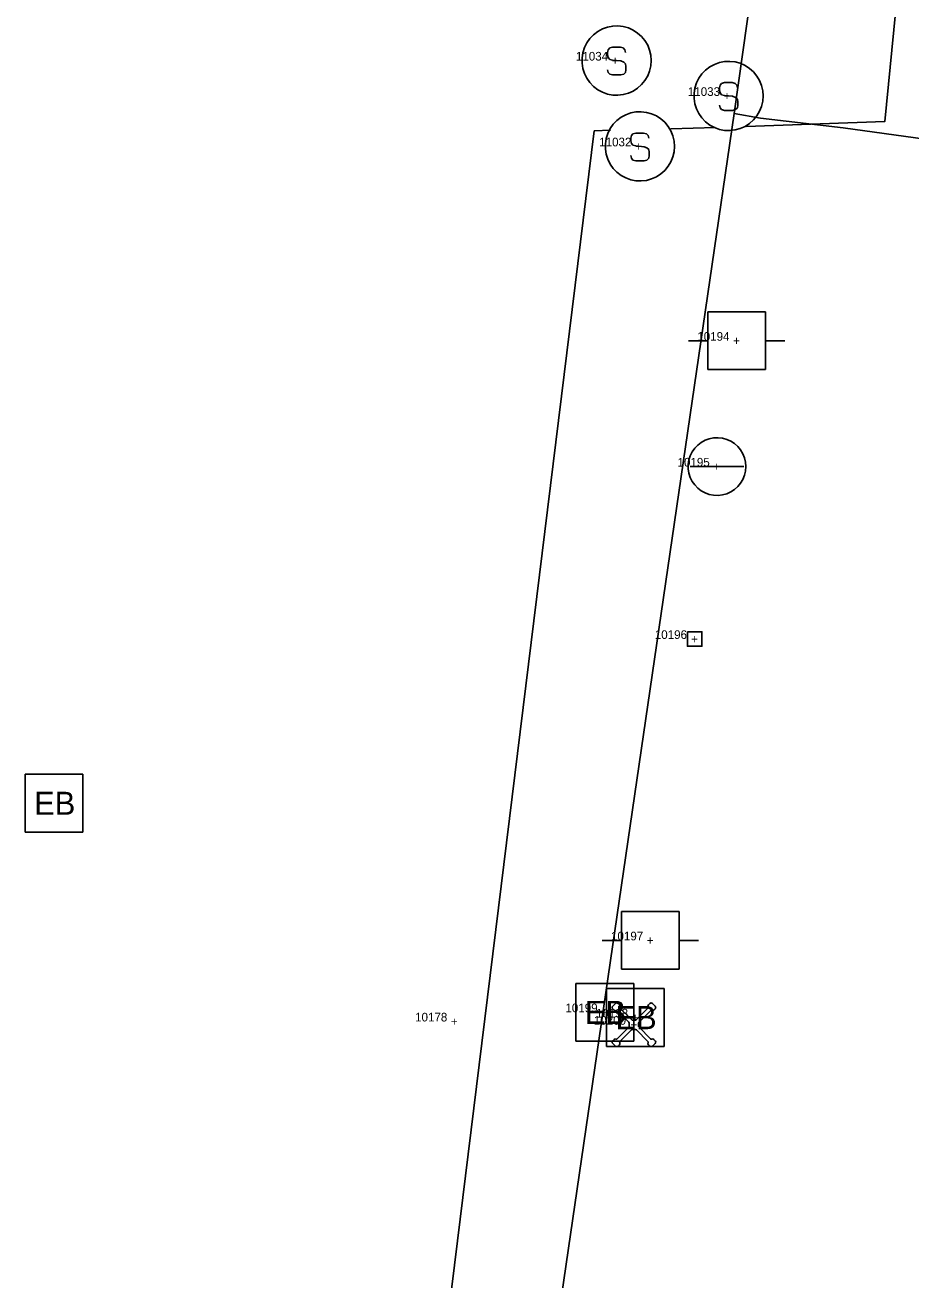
# Model space of a CAD drawing. Extents: x 1795905 to 1799611, y 243768 to 252016.
# Drawn here: x 1797887.3 to 1798040.7, y 247920.8 to 248138 of the extents above; entities that cross this region are included whole.
import ezdxf

# ---------------------------------------------------------------- set-up
doc = ezdxf.new("R2010")
doc.units = 0
for name, color, linetype in [('LS-SURVEY POINT', 7, 'Continuous'), ('OHUT', 7, 'Continuous'), ('TOPO', 7, 'Continuous'), ('UGUT', 7, 'Continuous'), ('UGUTTXT', 7, 'Continuous')]:
    doc.layers.add(name, color=color, linetype=linetype)

msp = doc.modelspace()

# ---------------------------------------------------------------- linework, layer by layer
at = {"layer": 'OHUT'}
for p, q in [((1798005.57, 248088.37), (1798015.57, 248088.37)), ((1798005.57, 248078.37), (1798005.57, 248088.37)), ((1798015.57, 248088.37), (1798015.57, 248078.37)), ((1798002.24, 248083.37), (1798005.57, 248083.37)), ((1798015.57, 248083.37), (1798018.91, 248083.37)), ((1798015.57, 248078.37), (1798005.57, 248078.37)), ((1797990.63, 247984.55), (1798000.63, 247984.55)), ((1797990.63, 247974.55), (1797990.63, 247984.55)), ((1798000.63, 247984.55), (1798000.63, 247974.55)), ((1797987.3, 247979.55), (1797990.63, 247979.55)), ((1798000.63, 247979.55), (1798003.97, 247979.55)), ((1798000.63, 247974.55), (1797990.63, 247974.55))]:
    msp.add_line(p, q, dxfattribs=at)
at = {"layer": 'TOPO'}
msp.add_lwpolyline([(1798002.04, 248032.99), (1798004.54, 248032.99), (1798004.54, 248030.49), (1798002.04, 248030.49)], close=True, dxfattribs=at)
at = {"layer": 'UGUT'}
for p, q in [((1797988.19, 248132.84), (1797988.19, 248133.29)), ((1797988.32, 248132.39), (1797988.19, 248132.84)), ((1797988.58, 248132.07), (1797988.32, 248132.39)), ((1797990.94, 248134.06), (1797990.43, 248134.19)), ((1797991.2, 248133.74), (1797990.94, 248134.06)), ((1797991.33, 248133.29), (1797991.2, 248133.74)), ((1797988.19, 248130.28), (1797988.32, 248129.83)), ((1797989.09, 248131.95), (1797988.58, 248132.07)), ((1797990.5, 248131.82), (1797989.09, 248131.95)), ((1797990.5, 248131.82), (1797991.01, 248131.63)), ((1797991.33, 248131.31), (1797991.01, 248131.63)), ((1797991.39, 248130.86), (1797991.33, 248131.31)), ((1797991.33, 248129.83), (1797991.39, 248130.28)), ((1797991.39, 248130.28), (1797991.39, 248130.86)), ((1797988.32, 248129.83), (1797988.58, 248129.51)), ((1797988.58, 248129.51), (1797989.09, 248129.39)), ((1797989.09, 248129.39), (1797990.5, 248129.39)), ((1797990.5, 248129.39), (1797991.01, 248129.51)), ((1797991.01, 248129.51), (1797991.33, 248129.83)), ((1798010.32, 248127.94), (1798009.81, 248128.06)), ((1798010.58, 248127.62), (1798010.32, 248127.94)), ((1798007.57, 248126.72), (1798007.57, 248127.17)), ((1798007.7, 248126.27), (1798007.57, 248126.72)), ((1798007.95, 248125.95), (1798007.7, 248126.27)), ((1798008.47, 248125.82), (1798007.95, 248125.95)), ((1798009.87, 248125.7), (1798008.47, 248125.82)), ((1798009.87, 248125.7), (1798010.39, 248125.5)), ((1798010.71, 248127.17), (1798010.58, 248127.62)), ((1798007.57, 248124.16), (1798007.7, 248123.71)), ((1798007.7, 248123.71), (1798007.95, 248123.39)), ((1798010.71, 248125.18), (1798010.39, 248125.5)), ((1798010.39, 248123.39), (1798010.71, 248123.71)), ((1798010.77, 248124.74), (1798010.71, 248125.18)), ((1798010.71, 248123.71), (1798010.77, 248124.16)), ((1798010.77, 248124.16), (1798010.77, 248124.74)), ((1798007.95, 248123.39), (1798008.47, 248123.26)), ((1798008.47, 248123.26), (1798009.87, 248123.26)), ((1798009.87, 248123.26), (1798010.39, 248123.39)), ((1797994.98, 248119.21), (1797994.46, 248119.34)), ((1797995.23, 248118.89), (1797994.98, 248119.21)), ((1797992.22, 248117.99), (1797992.22, 248118.44)), ((1797992.35, 248117.54), (1797992.22, 248117.99)), ((1797992.61, 248117.22), (1797992.35, 248117.54)), ((1797993.12, 248117.1), (1797992.61, 248117.22)), ((1797994.53, 248116.97), (1797993.12, 248117.1)), ((1797994.53, 248116.97), (1797995.04, 248116.78)), ((1797995.36, 248118.44), (1797995.23, 248118.89)), ((1797992.22, 248115.43), (1797992.35, 248114.98)), ((1797992.35, 248114.98), (1797992.61, 248114.66)), ((1797995.36, 248116.46), (1797995.04, 248116.78)), ((1797995.04, 248114.66), (1797995.36, 248114.98)), ((1797995.42, 248116.01), (1797995.36, 248116.46)), ((1797995.36, 248114.98), (1797995.42, 248115.43)), ((1797995.42, 248115.43), (1797995.42, 248116.01)), ((1797992.61, 248114.66), (1797993.12, 248114.54)), ((1797993.12, 248114.54), (1797994.53, 248114.54)), ((1797994.53, 248114.54), (1797995.04, 248114.66)), ((1798002.49, 248061.59), (1798011.82, 248061.59)), ((1797887.34, 247998.31), (1797887.34, 248008.33)), ((1797887.34, 248008.33), (1797897.35, 248008.33)), ((1797897.35, 248008.33), (1797897.35, 247998.31)), ((1797897.35, 247998.31), (1797887.34, 247998.31)), ((1797982.73, 247962.1), (1797982.73, 247972.11)), ((1797982.73, 247972.11), (1797992.75, 247972.11)), ((1797992.75, 247972.11), (1797992.75, 247962.1)), ((1797988.02, 247961.19), (1797988.02, 247971.2)), ((1797988.02, 247971.2), (1797998.04, 247971.2)), ((1797998.04, 247971.2), (1797998.04, 247961.19)), ((1797989.1, 247968.16), (1797989.56, 247968.62)), ((1797989.1, 247967.7), (1797989.33, 247967.47)), ((1797989.88, 247967.37), (1797991.89, 247965.37)), ((1797990.02, 247968.62), (1797990.25, 247968.39)), ((1797990.34, 247967.83), (1797992.35, 247965.83)), ((1797995.21, 247967.83), (1797993.21, 247965.83)), ((1797995.67, 247967.37), (1797993.67, 247965.37)), ((1797995.54, 247968.62), (1797995.3, 247968.39)), ((1797995.99, 247968.62), (1797996.45, 247968.16)), ((1797996.45, 247967.7), (1797996.22, 247967.47)), ((1797989.88, 247962.51), (1797991.89, 247964.51)), ((1797990.34, 247962.05), (1797992.35, 247964.05)), ((1797995.21, 247962.05), (1797993.21, 247964.05)), ((1797995.67, 247962.51), (1797993.67, 247964.51)), ((1797992.75, 247962.1), (1797982.73, 247962.1)), ((1797998.04, 247961.19), (1797988.02, 247961.19)), ((1797989.1, 247962.18), (1797989.33, 247962.41)), ((1797989.1, 247961.72), (1797989.56, 247961.26)), ((1797990.02, 247961.26), (1797990.25, 247961.49)), ((1797995.54, 247961.26), (1797995.3, 247961.49)), ((1797995.99, 247961.26), (1797996.45, 247961.72)), ((1797996.45, 247962.18), (1797996.22, 247962.41))]:
    msp.add_line(p, q, dxfattribs=at)
for points in [[(1797995.78, 248131.88), (1797995.71, 248132.8), (1797995.5, 248133.69), (1797995.16, 248134.54), (1797994.69, 248135.33), (1797994.11, 248136.04), (1797993.42, 248136.65), (1797992.65, 248137.15), (1797991.81, 248137.53), (1797990.93, 248137.77), (1797990.01, 248137.88), (1797989.1, 248137.84), (1797988.19, 248137.67), (1797987.33, 248137.35), (1797986.52, 248136.92), (1797985.79, 248136.36), (1797985.15, 248135.7), (1797984.63, 248134.95), (1797984.22, 248134.12), (1797983.94, 248133.25), (1797983.8, 248132.34), (1797983.8, 248131.42), (1797983.94, 248130.51), (1797984.22, 248129.64), (1797984.63, 248128.81), (1797985.15, 248128.06), (1797985.79, 248127.4), (1797986.52, 248126.84), (1797987.33, 248126.41), (1797988.19, 248126.09), (1797989.1, 248125.92), (1797990.01, 248125.88), (1797990.93, 248125.99), (1797991.81, 248126.23), (1797992.65, 248126.61), (1797993.42, 248127.11), (1797994.11, 248127.72), (1797994.69, 248128.43), (1797995.16, 248129.22), (1797995.5, 248130.07), (1797995.71, 248130.96)], [(1798015.16, 248125.76), (1798015.09, 248126.67), (1798014.88, 248127.57), (1798014.54, 248128.42), (1798014.07, 248129.21), (1798013.48, 248129.92), (1798012.8, 248130.53), (1798012.03, 248131.03), (1798011.19, 248131.41), (1798010.3, 248131.65), (1798009.39, 248131.75), (1798008.47, 248131.72), (1798007.57, 248131.54), (1798006.71, 248131.23), (1798005.9, 248130.8), (1798005.17, 248130.24), (1798004.53, 248129.58), (1798004, 248128.83), (1798003.6, 248128), (1798003.32, 248127.13), (1798003.18, 248126.22), (1798003.18, 248125.3), (1798003.32, 248124.39), (1798003.6, 248123.52), (1798004, 248122.69), (1798004.53, 248121.94), (1798005.17, 248121.28), (1798005.9, 248120.72), (1798006.71, 248120.28), (1798007.57, 248119.97), (1798008.47, 248119.8), (1798009.39, 248119.76), (1798010.3, 248119.87), (1798011.19, 248120.11), (1798012.03, 248120.49), (1798012.8, 248120.99), (1798013.48, 248121.6), (1798014.07, 248122.31), (1798014.54, 248123.1), (1798014.88, 248123.95), (1798015.09, 248124.84)], [(1797999.81, 248117.03), (1797999.74, 248117.95), (1797999.53, 248118.84), (1797999.19, 248119.69), (1797998.72, 248120.48), (1797998.14, 248121.19), (1797997.45, 248121.8), (1797996.68, 248122.3), (1797995.84, 248122.68), (1797994.96, 248122.92), (1797994.04, 248123.03), (1797993.13, 248122.99), (1797992.22, 248122.82), (1797991.36, 248122.51), (1797990.55, 248122.07), (1797989.82, 248121.51), (1797989.19, 248120.85), (1797988.66, 248120.1), (1797988.25, 248119.27), (1797987.97, 248118.4), (1797987.83, 248117.49), (1797987.83, 248116.57), (1797987.97, 248115.66), (1797988.25, 248114.79), (1797988.66, 248113.96), (1797989.19, 248113.21), (1797989.82, 248112.55), (1797990.55, 248111.99), (1797991.36, 248111.56), (1797992.22, 248111.24), (1797993.13, 248111.07), (1797994.04, 248111.04), (1797994.96, 248111.14), (1797995.84, 248111.38), (1797996.68, 248111.76), (1797997.45, 248112.26), (1797998.14, 248112.87), (1797998.72, 248113.58), (1797999.19, 248114.37), (1797999.53, 248115.22), (1797999.74, 248116.11)], [(1798012.16, 248061.59), (1798012.1, 248062.35), (1798011.92, 248063.1), (1798011.64, 248063.81), (1798011.25, 248064.46), (1798010.76, 248065.05), (1798010.19, 248065.56), (1798009.54, 248065.98), (1798008.85, 248066.29), (1798008.11, 248066.5), (1798007.35, 248066.58), (1798006.58, 248066.55), (1798005.83, 248066.41), (1798005.11, 248066.15), (1798004.44, 248065.78), (1798003.83, 248065.32), (1798003.3, 248064.77), (1798002.86, 248064.14), (1798002.52, 248063.46), (1798002.29, 248062.73), (1798002.17, 248061.97), (1798002.17, 248061.2), (1798002.29, 248060.45), (1798002.52, 248059.72), (1798002.86, 248059.03), (1798003.3, 248058.41), (1798003.83, 248057.85), (1798004.44, 248057.39), (1798005.11, 248057.02), (1798005.83, 248056.77), (1798006.58, 248056.62), (1798007.35, 248056.59), (1798008.11, 248056.68), (1798008.85, 248056.88), (1798009.54, 248057.19), (1798010.19, 248057.61), (1798010.76, 248058.12), (1798011.25, 248058.71), (1798011.64, 248059.37), (1798011.92, 248060.08), (1798012.1, 248060.82)]]:
    msp.add_lwpolyline(points, close=True, dxfattribs=at)
for points in [[(1797988.19, 248133.29), (1797988.32, 248133.74), (1797988.58, 248134.06)], [(1797990.43, 248134.19), (1797989.09, 248134.19), (1797988.58, 248134.06)], [(1798007.57, 248127.17), (1798007.7, 248127.62), (1798007.95, 248127.94)], [(1798009.81, 248128.06), (1798008.47, 248128.06), (1798007.95, 248127.94)], [(1797992.22, 248118.44), (1797992.35, 248118.89), (1797992.61, 248119.21)], [(1797994.46, 248119.34), (1797993.12, 248119.34), (1797992.61, 248119.21)]]:
    msp.add_lwpolyline(points, dxfattribs=at)
for centre, radius, start, end in [((1797989.33, 247967.93), 0.325, 135, 225), ((1797989.56, 247967.7), 0.325, 225, 295.5288), ((1797989.79, 247968.39), 0.325, 45, 135), ((1797989.77, 247967.26), 0.163, 45, 115.5288), ((1797990.02, 247968.16), 0.325, 334.4712, 45), ((1797990.46, 247967.95), 0.163, 154.4712, 225), ((1797995.53, 247968.16), 0.325, 135, 205.5288), ((1797995.09, 247967.95), 0.163, 315, 25.5288), ((1797995.76, 247968.39), 0.325, 45, 135), ((1797995.78, 247967.26), 0.163, 64.4712, 135), ((1797995.99, 247967.7), 0.325, 244.4712, 315), ((1797996.22, 247967.93), 0.325, 315, 45), ((1797991.66, 247965.14), 0.325, 349.8499, 45), ((1797992.78, 247964.94), 0.813, 169.8499, 190.1501), ((1797992.58, 247966.06), 0.325, 225, 280.1501), ((1797992.78, 247964.94), 0.813, 79.8499, 100.1501), ((1797992.98, 247966.06), 0.325, 259.8499, 315), ((1797993.9, 247965.14), 0.325, 135, 190.1501), ((1797992.78, 247964.94), 0.813, 349.8499, 10.1501), ((1797991.66, 247964.74), 0.325, 315, 10.1501), ((1797992.58, 247963.82), 0.325, 79.8499, 135), ((1797992.78, 247964.94), 0.813, 259.8499, 280.1501), ((1797992.98, 247963.82), 0.325, 45, 100.1501), ((1797993.9, 247964.74), 0.325, 169.8499, 225), ((1797989.33, 247961.95), 0.325, 135, 225), ((1797989.56, 247962.18), 0.325, 64.4712, 135), ((1797989.79, 247961.49), 0.325, 225, 315), ((1797989.77, 247962.62), 0.163, 244.4712, 315), ((1797990.02, 247961.72), 0.325, 315, 25.5288), ((1797990.46, 247961.93), 0.163, 135, 205.5288), ((1797995.09, 247961.93), 0.163, 334.4712, 45), ((1797995.53, 247961.72), 0.325, 154.4712, 225), ((1797995.76, 247961.49), 0.325, 225, 315), ((1797995.78, 247962.62), 0.163, 225, 295.5288), ((1797995.99, 247962.18), 0.325, 45, 115.5288), ((1797996.22, 247961.95), 0.325, 315, 45)]:
    msp.add_arc(centre, radius, start, end, dxfattribs=at)
at = {"layer": 'UGUTTXT'}
for p, q in [((1797942.79, 247769.31), (1797985.87, 248119.72)), ((1797985.87, 248119.72), (1797988.7, 248119.84)), ((1797999.14, 248120.06), (1798006.9, 248120.27))]:
    msp.add_line(p, q, dxfattribs=at)
for points in [[(1798019.65, 248190.19), (1798010.15, 248122.69)], [(1798012.19, 248120.44), (1798036.25, 248121.35), (1798038.05, 248140.12), (1798020.27, 248146.4)], [(1798010.15, 248122.69), (1797958.43, 247768.51)], [(1798014.69, 248121.9), (1798010.15, 248122.69)], [(1798029.04, 248120.23), (1798014.69, 248121.9)], [(1798048.66, 248117.55), (1798029.04, 248120.23)]]:
    msp.add_lwpolyline(points, dxfattribs=at)

# ---------------------------------------------------------------- texts
at = {"layer": 'LS-SURVEY POINT'}
for s, p in [('11034', (1797982.73, 248131.88)), ('+', (1797988.93, 248131.13)), ('11033', (1798002.11, 248125.76)), ('+', (1798008.31, 248125.01)), ('11032', (1797986.76, 248117.03)), ('+', (1797992.96, 248116.28)), ('10194', (1798003.75, 248083.37)), ('+', (1798009.95, 248082.62)), ('10195', (1798000.33, 248061.59)), ('+', (1798006.53, 248060.84)), ('10196', (1797996.39, 248031.74)), ('+', (1798002.66, 248030.99)), ('10197', (1797988.81, 247979.55)), ('+', (1797995.01, 247978.8)), ('10199', (1797980.91, 247967.11)), ('10198', (1797986.2, 247966.19)), ('+', (1797987.11, 247966.36)), ('10178', (1797954.88, 247965.51)), ('+', (1797961.08, 247964.76)), ('10200', (1797985.83, 247964.94)), ('+', (1797992.15, 247964.19)), ('+', (1797992.4, 247965.44))]:
    msp.add_text(s, height=1.5, dxfattribs=at).set_placement(p)
at = {"layer": 'TOPO'}
msp.add_text('+', height=0.1, dxfattribs=at).set_placement((1798003.25, 248031.69))
at = {"layer": 'UGUT'}
for p in [(1797888.9, 248001.29), (1797984.29, 247965.08), (1797989.58, 247964.17)]:
    msp.add_text('EB', height=4, dxfattribs=at).set_placement(p)

doc.saveas('drawing.dxf')
